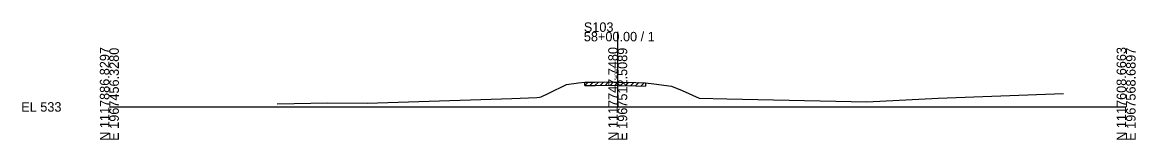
# Model space of a CAD drawing. Extents: x 974 to 1303, y 990 to 14518.
# Drawn here: x 974.3 to 1302.8, y 4990.3 to 5025 of the extents above; entities that cross this region are included whole.
import ezdxf

# ---------------------------------------------------------------- set-up
doc = ezdxf.new("R2010")
doc.units = 0
for name, color, linetype in [('Level 10', 7, 'Continuous'), ('Level 60', 7, 'Continuous'), ('Level 61', 7, 'Continuous'), ('Level 63', 7, 'Continuous')]:
    doc.layers.add(name, color=color, linetype=linetype)

msp = doc.modelspace()

# ---------------------------------------------------------------- linework, layer by layer
at = {"layer": 'Level 60'}
for p, q in [((1134.9, 5006.66), (1138.44, 5007.08)), ((1138.44, 5007.08), (1140.29, 5007.29)), ((1140.29, 5007.29), (1143.36, 5007.32)), ((1143.36, 5007.32), (1149.1, 5007.39)), ((1149.1, 5007.39), (1150, 5007.36)), ((1150, 5007.36), (1155.33, 5007.21)), ((1155.33, 5007.21), (1158.17, 5007.13)), ((1158.17, 5007.13), (1160.65, 5006.83)), ((1127.44, 5002.94), (1129.7, 5004.08)), ((1129.7, 5004.08), (1134.9, 5006.66)), ((1160.65, 5006.83), (1165.84, 5006.18)), ((1165.84, 5006.18), (1168.98, 5004.87)), ((1168.98, 5004.87), (1174.07, 5002.54)), ((1244.59, 5002.61), (1281.48, 5003.97)), ((1049.53, 5000.92), (1064.46, 5001.22)), ((1064.46, 5001.22), (1076.09, 5001.15)), ((1076.09, 5001.15), (1118.74, 5002.45)), ((1118.74, 5002.45), (1126.1, 5002.75)), ((1126.1, 5002.75), (1126.89, 5002.87)), ((1126.89, 5002.87), (1127.44, 5002.94)), ((1174.07, 5002.54), (1182.16, 5002.41)), ((1182.16, 5002.41), (1223.5, 5001.5)), ((1223.5, 5001.5), (1244.59, 5002.61))]:
    msp.add_line(p, q, dxfattribs=at)
at = {"layer": 'Level 61'}
for p, q in [((1140.29, 5006.29), (1141.3, 5007.3)), ((1140.29, 5006.29), (1140.29, 5007.29)), ((1141.79, 5006.3), (1142.8, 5007.31)), ((1143.29, 5006.32), (1144.3, 5007.33)), ((1144.79, 5006.34), (1145.8, 5007.35)), ((1146.29, 5006.36), (1147.3, 5007.37)), ((1147.79, 5006.37), (1148.8, 5007.39)), ((1149.29, 5006.38), (1150.26, 5007.36)), ((1150.79, 5006.34), (1151.76, 5007.31)), ((1152.29, 5006.3), (1153.26, 5007.27)), ((1153.79, 5006.26), (1154.76, 5007.23)), ((1155.29, 5006.21), (1156.26, 5007.19)), ((1156.79, 5006.17), (1157.76, 5007.14)), ((1158.17, 5007.13), (1158.17, 5006.13)), ((1140.29, 5006.29), (1143.36, 5006.32)), ((1140.29, 5006.29), (1140.29, 5006.29)), ((1143.36, 5006.32), (1149.1, 5006.39)), ((1149.1, 5006.39), (1150, 5006.36)), ((1150, 5006.36), (1155.33, 5006.21)), ((1155.33, 5006.21), (1158.17, 5006.13))]:
    msp.add_line(p, q, dxfattribs=at)
at = {"layer": 'Level 63'}
for p, q in [((1150, 5000), (1150, 5022.17)), ((1000, 5000), (1150, 5000)), ((1150, 5000), (1300, 5000))]:
    msp.add_line(p, q, dxfattribs=at)

# ---------------------------------------------------------------- texts
at = {"layer": 'Level 10'}
msp.add_text('540.36', height=0.9, rotation=90, dxfattribs=at).set_placement((1149.95, 5007.86))
at = {"layer": 'Level 63'}
for s, p in [('S103', (1140, 5022.17)), ('58+00.00 / 1', (1140, 5019.37)), ('EL 533', (974, 4998.6))]:
    msp.add_text(s, height=2.8, dxfattribs=at).set_placement(p)
for s, p in [('N 1117886.8297', (1000, 4990)), ('E 1967456.3280', (1002.8, 4990)), ('N 1117747.7480', (1150, 4990)), ('E 1967512.5089', (1152.8, 4990)), ('N 1117608.6663', (1300, 4990)), ('E 1967568.6897', (1302.8, 4990))]:
    msp.add_text(s, height=2.8, rotation=90, dxfattribs=at).set_placement(p)

doc.saveas('drawing.dxf')
